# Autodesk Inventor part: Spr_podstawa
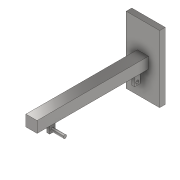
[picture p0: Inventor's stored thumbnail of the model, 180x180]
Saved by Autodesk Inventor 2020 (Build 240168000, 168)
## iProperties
Created: 2021-01
Part Number: Spr_podstawa
Material: Stal, węglowa
Document SubType Name: Modeling
Designer: Home
Mass: 1217.78 g
Surface Area: 360.859 cm^2
Volume: 155.131 cm^3
Density: 7.85 g/cm^3
Appearance: Częściowo polerowany
Author: Home
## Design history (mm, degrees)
sketch "Szkic1"
  geometry: L1 (-30, -60)-(30, -60); L2 (30, -60)-(30, 60); L3 (30, 60)-(-30, 60); L4 (-30, 60)-(-30, -60); L5 (-30, -60)-(30, 60); L6 (30, -60)-(-30, 60); 1 further point
  constraints: 12 end point, 2 midpoint, 2 parallel, 1 horizontal, 1 perpendicular
  dimensions: "d0" = 60 distance of L3.end L2.end; "d1" = 120 distance of L2.end L1.end
extrude "Wyciągnięcie proste1" new body sketch "Szkic1" distance "d2" = 10; taper "d3" = 0 deg
sketch "Szkic2"
  geometry: L1 (-10, -10)-(10, -10); L2 (10, -10)-(10, 10); L3 (10, 10)-(-10, 10); L4 (-10, 10)-(-10, -10); L5 (-10, -10)-(10, 10); L6 (10, -10)-(-10, 10); 1 further point
  constraints: 12 end point, 2 midpoint, 2 parallel, 1 horizontal, 1 perpendicular
  dimensions: "d4" = 20 distance of L3.end L2.end; "d5" = 20 distance of L2.end L1.end
extrude "Wyciągnięcie proste2" join sketch "Szkic2" distance "d6" = 200; taper "d7" = 0 deg
sketch "Szkic3"
  geometry: L1 (0, 180)-(-30, 180); L2 (-30, 180)-(-30, 170); L3 (-30, 170)-(0, 170); L4 (0, 170)-(0, 180); L5 (0, 30)-(-30, 30); L6 (-30, 30)-(-30, 20); L7 (-30, 20)-(0, 20); L8 (0, 20)-(0, 30); L9 (60, 0)-(-60, 0) reference; C1 r 3 at (-25, 175); C2 r 3 at (-25, 25); 3 further points
  constraints: 16 end point, 4 parallel, 3 vertical alignment, 2 centre point, 2 horizontal, 2 horizontal alignment, 2 midpoint, 2 perpendicular, 2 point on line
  dimensions: "d8" = 10 distance of L1.end L2.end; "d9" = 10 distance of L5.end L6.end; "d10" = 20 distance between parallel lines of L9 L7; "d11" = 150 distance between parallel lines of L3 L7; "d12" = 30 distance between parallel lines of L6 L8; "d13" = 6 diameter of C1; "d14" = 6 diameter of C2; "d15" = 5 distance from line of L2 C1.centre
extrude "Wyciągnięcie proste3" join sketch "Szkic3" distance "d16" = 5; taper "d17" = 0 deg
extrude "Wyciągnięcie proste4" join sketch "Szkic3" stored distance "d18" = 5; taper "d19" = 0 deg
extrude "Wyciągnięcie proste5" join sketch "Szkic3" stored distance "d20" = 50; taper "d21" = 0 deg
node "Bryła1"
